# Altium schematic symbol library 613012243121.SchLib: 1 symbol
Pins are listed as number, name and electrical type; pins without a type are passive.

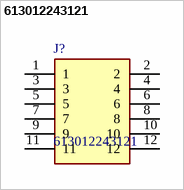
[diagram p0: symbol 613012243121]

## 613012243121
designator J?
WURTH ELEKTRONIK - 613012243121 - CONNECTOR, RCPT, 12POS, 2ROW, 2.54MM; Geometry.Height: 5.23mm
footprint 613012243121
pins: 1, 2, 3, 4, 5, 6, 7, 8, 9, 10, 11, 12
